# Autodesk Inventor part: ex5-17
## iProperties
Shininess: 64.0
Length Units: 11272
Angle Units: 11279
Time Units: 11290
Mass Units: 11286
Length Display Precision: 3
Angle Display Precision: 2
Compacted: True
Part Number: ex5-17
Document SubType Name: Modeling
Created: 2002-09
Designer: Elise Moss
Density: 0.0
Volumn: 0.0
Area: 0.0
PropertySet Name: Model Information
Control State: 0
Master: False
Checked Out: False
Author: Elise Moss
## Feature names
1. Revolution1
2. Hole1
3. Shell1
4. Loft1
5. Sweep1
6. Mirror1
